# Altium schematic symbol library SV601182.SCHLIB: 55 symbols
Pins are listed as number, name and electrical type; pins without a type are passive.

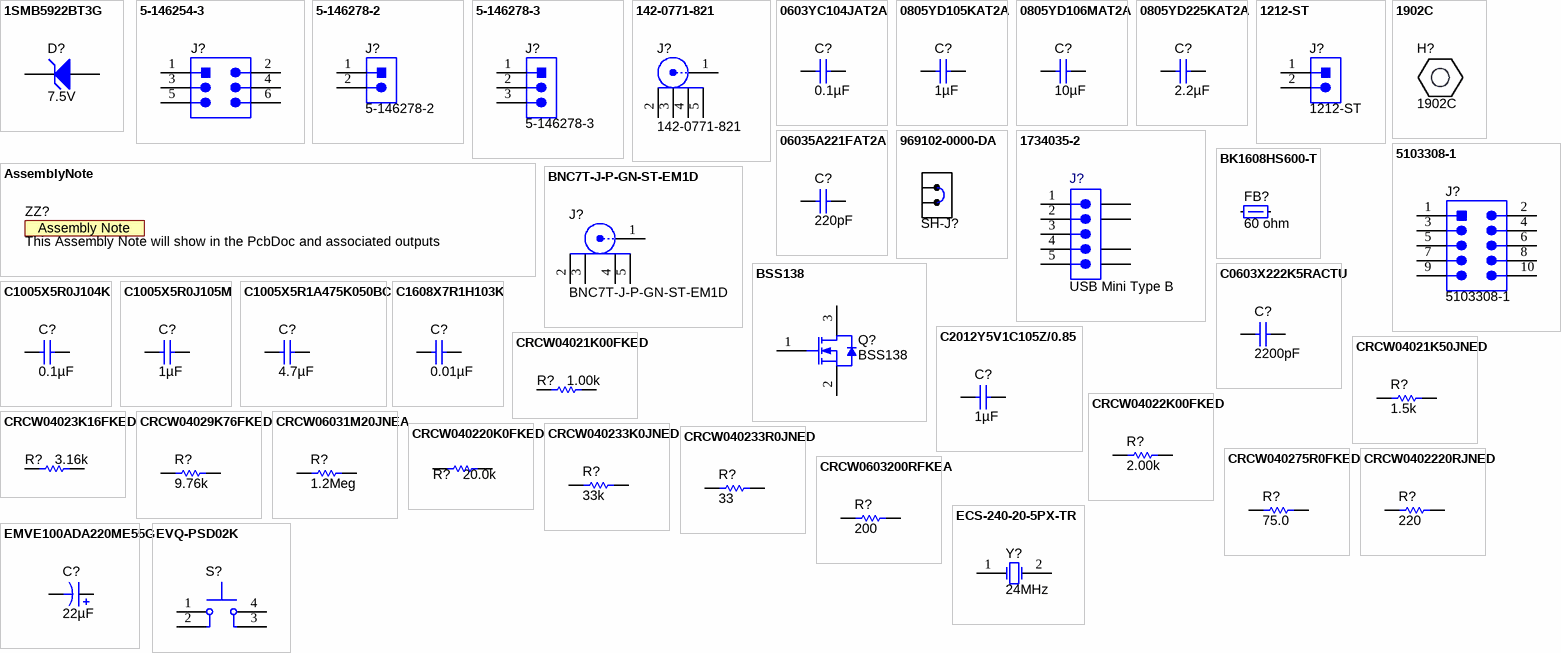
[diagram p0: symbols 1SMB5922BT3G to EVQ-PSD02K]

## 1SMB5922BT3G
designator D?  value 7.5V  (hidden comment: 1SMB5922BT3G)
Diode, Zener, 7.5 V, 550 mW, SMB; Manufacturer: ON Semiconductor; SymbolCreator: a0412235; U/M: EA; Power_W: 0.55; Vz_V: 7.5; Value1: 0.55W; RJA_CperW: 226
signal-integrity model Diode
simulation model 1smb5922bt3
footprint SMB
pins: 1 K, 2 A

## 5-146254-3
designator J?  (value not drawn)
Header, 100mil, 3x2, Tin, TH; Manufacturer: TE Connectivity; SymbolCreator: a0412235; U/M: EA
footprint TE_5-146254-3
pins: 1, 2, 3, 4, 5, 6

## 5-146278-2
designator J?
Header, 100mil, 2x1, Tin, TH; Manufacturer: TE Connectivity; SymbolCreator: a0412235; U/M: EA
footprint TE_5-146278-2
pins: 1, 2
1 alternate drawing of the same symbol

## 5-146278-3
designator J?
Header, 100mil, 3x1, Tin, TH; Manufacturer: TE Connectivity; SymbolCreator: a0799628; U/M: EA
footprint TE_5-146278-3
pins: 1, 2, 3
2 alternate drawings of the same symbol

## 142-0771-821
designator J?
Connector, TH, End launch SMA 50 ohm; Manufacturer: Emerson Network Power; SymbolCreator: X0208326; U/M: EA
footprint Emerson_142-0771-821
pins: 1, 2, 3, 4, 5

## 0603YC104JAT2A
designator C?  ValueDisplayed: 0.1µF  (hidden comment: 0603YC104JAT2A)
CAP, CERM, 0.1uF, 16V, +/-5%, X7R, 0603; Manufacturer: AVX; Polarized: N; CompType: Capacitor; U/M: EA; Cap_F: 0.0000001; Tolerance_%: 5; ESR_Ohm: 0.039; Value1: 0.039 ohm; VDC_V: 16; TaMin_C: -55; TaMax_C: 125; Cap_Case: 0603
signal-integrity model Cap
simulation model Cap
footprint 0603
footprint 0603M
footprint 0603L
footprint 0603_HV
footprint C603
pins: 1, 2

## 0805YD105KAT2A
designator C?  ValueDisplayed: 1µF  (hidden comment: 0805YD105KAT2A)
CAP, CERM, 1uF, 16V, +/-10%, X5R, 0805; Manufacturer: AVX; Polarized: N; CompType: Capacitor; U/M: EA; Cap_F: 0.000001; Tolerance_%: 10; ESR_Ohm: 0.012; Value1: 0.012 ohm; VDC_V: 16; TaMin_C: -55; TaMax_C: 85; Cap_Case: 0805
signal-integrity model Cap
simulation model Cap
footprint 0805_HV
footprint 0805
footprint 0805M
footprint 0805L
pins: 1, 2

## 0805YD106MAT2A
designator C?  ValueDisplayed: 10µF  (hidden comment: 0805YD106MAT2A)
CAP, CERM, 10uF, 16V, +/-20%, X5R, 0805; Manufacturer: AVX; Polarized: N; CompType: Capacitor; U/M: EA; Cap_F: 0.00001; Tolerance_%: 20; Value1: Unknown; VDC_V: 16; TaMin_C: -55; TaMax_C: 85; Cap_Case: 0805
signal-integrity model Cap
simulation model Cap
footprint 0805_HV
footprint 0805
footprint 0805M
footprint 0805L
pins: 1, 2

## 0805YD225KAT2A
designator C?  ValueDisplayed: 2.2µF  (hidden comment: 0805YD225KAT2A)
CAP, CERM, 2.2uF, 16V, +/-10%, X5R, 0805; Manufacturer: AVX; Polarized: N; CompType: Capacitor; U/M: EA; Cap_F: 0.0000022; Tolerance_%: 10; ESR_Ohm: 0.009; Value1: 0.009 ohm; VDC_V: 16; TaMin_C: -55; TaMax_C: 85; Cap_Case: 0805
signal-integrity model Cap
simulation model Cap
footprint 0805_HV
footprint 0805
footprint 0805M
footprint 0805L
footprint C0805
pins: 1, 2

## 1212-ST
designator J?
Disconnect Terminal, 5.08mm, 2x1, Tin, TH; Manufacturer: Keystone; SymbolCreator: a0412235; U/M: EA
footprint Keystone_1212-ST
pins: 1, 2
1 alternate drawing of the same symbol

## 1902C
designator H?
Standoff, Hex, 0.5"L #4-40 Nylon; Manufacturer: Keystone; CompType: Hardware; SymbolCreator: a0412235
footprint Keystone_1902C

## 06035A221FAT2A
designator C?  ValueDisplayed: 220pF  (hidden comment: 06035A221FAT2A)
CAP, CERM, 220pF, 50V, +/-1%, C0G/NP0, 0603; Manufacturer: AVX; Polarized: N; CompType: Capacitor; U/M: EA; Cap_F: 0.00000000022; Tolerance_%: 1; ESR_Ohm: 0.083; Value1: 0.083 ohm; VDC_V: 50; TaMin_C: -55; TaMax_C: 125; Cap_Case: 0603
signal-integrity model Cap
simulation model Cap
footprint 0603
footprint 0603M
footprint 0603L
footprint 0603_HV
footprint C603
pins: 1, 2

## 969102-0000-DA
designator SH-J?  (value not drawn)
Shunt, 100mil, Gold plated, Black; Manufacturer: 3M; Alternate Manufacturer: Samtec; Alternate PartNumber: SNT-100-BK-G; Value: 1x2; Note: You can "mate" this to a header by matching the designator.  i.e. use SH-J3 for header J3
footprint SNT-100-BK-G

## 1734035-2
designator J?, comment USB Mini Type B
Connector, Receptacle, Mini-USB Type B, R/A, Top Mount SMT; Manufacturer: TE Connectivity; PartNumber: 1734035-2; SymbolCreator: A0412235; U/M: EA
footprint CONN_USB-Mini-B-1734035-2
pins: 1, 2, 3, 4, 5, 6 GND, 7 GND, 8 GND, 9 GND

## 5103308-1
designator J?
Header (shrouded), 100mil, 5x2, Gold, TH; Manufacturer: TE Connectivity; SymbolCreator: a0412235; U/M: EA
footprint CONN_5103308-1
pins: 1, 2, 3, 4, 5, 6, 7, 8, 9, 10

## AssemblyNote
designator ZZ?, comment This Assembly Note will show in the PcbDoc and associated outputs  (no BOM)
SymbolCreator: codlsc
footprint AssemblyNote

## BK1608HS600-T
designator FB?  value 60 ohm  (hidden comment: BK1608HS600-T)
Ferrite Bead, 60 ohm @ 100 MHz, 0.8 A, 0603; Manufacturer: Taiyo Yuden; Imax_A: 0.8; DCR_ohm: 0.1; Value1: 0.1 ohm; Value2: 0.8A; ZTyp@100MHz_Ohm: 60
footprint 0603
footprint 0603M
footprint 0603L
footprint 0603_HV
footprint 0603S
pins: 1, 2

## BNC7T-J-P-GN-ST-EM1D
designator J?
Connector, BNC Edge Mount, SMD; Manufacturer: Samtec; SymbolCreator: Altium; U/M: EA
footprint SAMTEC_BNC7T-J-P-GN-ST-EM1D
pins: 1, 2, 3, 4, 5

## BSS138
designator Q?
MOSFET, N-CH, 50 V, 0.22 A, SOT-23; Manufacturer: Fairchild Semiconductor; Alternate Manufacturer: None; U/M: EA; ChType: N; Value: 50V; VdsMax_V: 50; Value1: 6 ohm; Rdson45_ohm: 6; Value2: 1.7 nC; QgTyp_nC: 1.7; Vgs_V: 20; IdsMax_A: 0.22
footprint SOT-23
footprint SOT-23M
footprint SOT-23L
pins: 1 G, 2 S, 3 D

## C0603X222K5RACTU
designator C?  ValueDisplayed: 2200pF  (hidden comment: C0603X222K5RACTU)
CAP, CERM, 2200pF, 50V, +/-10%, X7R, 0603; Manufacturer: Kemet; Polarized: N; CompType: Capacitor; U/M: EA; Cap_F: 0.0000000022; Tolerance_%: 10; VDC_V: 50; TaMin_C: -55; TaMax_C: 125; Cap_Case: 0603
signal-integrity model Cap
simulation model Cap
footprint 0603
footprint 0603M
footprint 0603L
footprint 0603_HV
footprint C603
pins: 1, 2

## C1005X5R0J104K
designator C?  ValueDisplayed: 0.1µF  (hidden comment: C1005X5R0J104K)
CAP, CERM, 0.1uF, 6.3V, +/-10%, X5R, 0402; Manufacturer: TDK; Polarized: N; CompType: Capacitor; U/M: EA; Cap_F: 0.0000001; Tolerance_%: 10; ESR_Ohm: 0.0186; Value1: 0.0186 ohm; VDC_V: 6.3; TaMin_C: -55; TaMax_C: 85; Cap_Case: 0402
signal-integrity model Cap
simulation model Cap
footprint 0402
footprint 0402M
footprint 0402L
footprint 0402S
pins: 1, 2

## C1005X5R0J105M
designator C?  ValueDisplayed: 1µF  (hidden comment: C1005X5R0J105M)
CAP, CERM, 1 µF, 6.3 V, +/- 20%, X5R, 0402; Manufacturer: TDK; Polarized: N; CompType: Capacitor; Value: 1uF; U/M: EA; Cap_F: 0.000001; Tolerance_%: 20; ESR_ohm: 0.0079; Value1: 0.0079 ohm; VDC_V: 6.3; Value2: 6.3V; TaMin_C: -55; TaMax_C: 85; Cap_Case: 0402
signal-integrity model Cap
simulation model Cap
footprint 0402
footprint 0402M
footprint 0402L
footprint 0402S
pins: 1, 2

## C1005X5R1A475K050BC
designator C?  ValueDisplayed: 4.7µF  (hidden comment: C1005X5R1A475K050BC)
CAP, CERM, 4.7 µF, 10 V, +/- 10%, X5R, 0402; Manufacturer: TDK; Polarized: N; CompType: Capacitor; Value: 4.7uF; U/M: EA; Cap_F: 0.0000047; Tolerance_%: 10; Value1: Unknown; Value2: 10V; TaMin_C: -55; TaMax_C: 85; Cap_Case: 0402
signal-integrity model Cap
simulation model Cap
footprint 0402
footprint 0402M
footprint 0402L
footprint 0402S
pins: 1, 2

## C1608X7R1H103K
designator C?  ValueDisplayed: 0.01µF  (hidden comment: C1608X7R1H103K)
CAP, CERM, 0.01uF, 50V, +/-10%, X7R, 0603; Manufacturer: TDK; Polarized: N; CompType: Capacitor; U/M: EA; Cap_F: 0.00000001; Tolerance_%: 10; ESR_Ohm: 0.0539; Value1: 0.0539 ohm; VDC_V: 50; TaMin_C: -55; TaMax_C: 125; Cap_Case: 0603
signal-integrity model Cap
simulation model Cap
footprint 0603
footprint 0603M
footprint 0603L
footprint 0603_HV
footprint C603
pins: 1, 2

## C2012Y5V1C105Z/0.85
designator C?, comment ValueDisplayed: 1µF  (hidden comment: C2012X7R1C105K/1.25)
CAP CER 1UF 16V 10% X7R 0805; Manufacturer: TDK; Polarized: N; CompType: Capacitor; U/M: EA; Cap_F: 0.000001; Tolerance_%: 80; ESR_Ohm: 0.009; Value1: 0.009 ohm; VDC_V: 16; TaMin_C: -30; TaMax_C: 85; Cap_Case: 0805
signal-integrity model Cap
simulation model Cap
footprint 0805_HV
footprint 0805
footprint 0805M
footprint 0805L
footprint C0805
pins: 1, 2

## CRCW04021K00FKED
designator R?  value 1.00k  (hidden comment: CRCW04021K00FKED)
RES, 1.00k ohm, 1%, 0.063W, 0402; Manufacturer: Vishay-Dale; CompType: Resistor; Res_ohm: 1000; Value_Code: 1k00; Tolerance_%: 1; Power_W: 0.063; VDC_V: 50; TempCo: 100 ppm/C; EIA_Code: E96; U/M: EA
signal-integrity model Resistor
simulation model Resistor
footprint 0402
footprint 0402M
footprint 0402L
footprint 0402S
pins: 1, 2

## CRCW04021K50JNED
designator R?  value 1.5k  (hidden comment: CRCW04021K50JNED)
RES, 1.5k ohm, 5%, 0.063W, 0402; Manufacturer: Vishay-Dale; CompType: Resistor; Res_ohm: 1500; Value_Code: 1k50; Tolerance_%: 5; Power_W: 0.063; VDC_V: 50; TempCo: 200 ppm/C; EIA_Code: E24; U/M: EA
signal-integrity model Resistor
simulation model Resistor
footprint 0402
footprint 0402M
footprint 0402L
footprint 0402
pins: 1, 2

## CRCW04022K00FKED
designator R?  value 2.00k  (hidden comment: CRCW04022K00FKED)
RES, 2.00k ohm, 1%, 0.063W, 0402; Manufacturer: Vishay-Dale; CompType: Resistor; Res_ohm: 2000; Value_Code: 2k00; Tolerance_%: 1; Power_W: 0.063; VDC_V: 50; TempCo: 100 ppm/C; EIA_Code: E96; U/M: EA
signal-integrity model Resistor
simulation model Resistor
footprint 0402
footprint 0402M
footprint 0402L
footprint 0402S
pins: 1, 2

## CRCW04023K16FKED
designator R?  value 3.16k  (hidden comment: CRCW04023K16FKED)
RES, 3.16k ohm, 1%, 0.063W, 0402; Manufacturer: Vishay-Dale; CompType: Resistor; Res_ohm: 3160; Value_Code: 3k16; Tolerance_%: 1; Power_W: 0.063; VDC_V: 50; TempCo: 100 ppm/C; EIA_Code: E96; U/M: EA
signal-integrity model Resistor
simulation model Resistor
footprint 0402
footprint 0402M
footprint 0402L
footprint 0402S
pins: 1, 2

## CRCW04029K76FKED
designator R?  value 9.76k  (hidden comment: CRCW04029K76FKED)
RES, 9.76k ohm, 1%, 0.063W, 0402; Manufacturer: Vishay-Dale; CompType: Resistor; Res_ohm: 9760; Value_Code: 9k76; Tolerance_%: 1; Power_W: 0.063; VDC_V: 50; TempCo: 100 ppm/C; EIA_Code: E96; U/M: EA
signal-integrity model Resistor
simulation model Resistor
footprint 0402
footprint 0402M
footprint 0402L
footprint 0402S
pins: 1, 2

## CRCW06031M20JNEA
designator R?  value 1.2Meg  (hidden comment: CRCW06031M20JNEA)
RES, 1.2Meg ohm, 5%, 0.1W, 0603; Manufacturer: Vishay-Dale; CompType: Resistor; Res_ohm: 1200000; Value_Code: 1M20; Tolerance_%: 5; Power_W: 0.1; VDC_V: 75; TempCo: 200 ppm/C; EIA_Code: E24; U/M: EA
signal-integrity model Resistor
simulation model Resistor
footprint 0603
footprint 0603M
footprint 0603L
footprint 0603_HV
footprint R603
pins: 1, 2

## CRCW040220K0FKED
designator R?  value 20.0k  (hidden comment: CRCW040220K0FKED)
RES, 20.0k ohm, 1%, 0.063W, 0402; Manufacturer: Vishay-Dale; CompType: Resistor; Res_ohm: 20000; Value_Code: 20k0; Tolerance_%: 1; Power_W: 0.063; VDC_V: 50; TempCo: 100 ppm/C; EIA_Code: E96; U/M: EA
signal-integrity model Resistor
simulation model Resistor
footprint 0402
footprint 0402M
footprint 0402L
footprint 0402S
pins: 1, 2

## CRCW040233K0JNED
designator R?  value 33k  (hidden comment: CRCW040233K0JNED)
RES, 33k ohm, 5%, 0.063W, 0402; Manufacturer: Vishay-Dale; CompType: Resistor; Res_ohm: 33000; Value_Code: 33k0; Tolerance_%: 5; Power_W: 0.063; VDC_V: 50; TempCo: 200 ppm/C; EIA_Code: E24; U/M: EA
signal-integrity model Resistor
simulation model Resistor
footprint 0402
footprint 0402M
footprint 0402L
pins: 1, 2

## CRCW040233R0JNED
designator R?  value 33  (hidden comment: CRCW040233R0JNED)
RES, 33 ohm, 5%, 0.063W, 0402; Manufacturer: Vishay-Dale; CompType: Resistor; Value_Code: 33R0; Tolerance_%: 5; Power_W: 0.063; VDC_V: 50; TempCo: 200 ppm/C; EIA_Code: E24; U/M: EA
signal-integrity model Resistor
simulation model Resistor
footprint 0402
footprint 0402M
footprint 0402L
footprint 0402
pins: 1, 2

## CRCW040275R0FKED
designator R?  value 75.0  (hidden comment: CRCW040275R0FKED)
RES, 75.0 ohm, 1%, 0.063W, 0402; Manufacturer: Vishay-Dale; CompType: Resistor; Res_ohm: 75; Value_Code: 75R0; Tolerance_%: 1; Power_W: 0.063; VDC_V: 50; TempCo: 100 ppm/C; EIA_Code: E96; U/M: EA
signal-integrity model Resistor
simulation model Resistor
footprint 0402
footprint 0402M
footprint 0402L
footprint 0402S
pins: 1, 2

## CRCW0402220RJNED
designator R?  value 220  (hidden comment: CRCW0402220RJNED)
RES, 220 ohm, 5%, 0.063W, 0402; Manufacturer: Vishay-Dale; CompType: Resistor; Value_Code: 220R; Tolerance_%: 5; Power_W: 0.063; VDC_V: 50; TempCo: 200 ppm/C; EIA_Code: E24; U/M: EA
signal-integrity model Resistor
simulation model Resistor
footprint 0402
footprint 0402M
footprint 0402L
footprint 0402S
pins: 1, 2

## CRCW0603200RFKEA
designator R?  value 200  (hidden comment: CRCW0603200RFKEA)
RES, 200 ohm, 1%, 0.1W, 0603; Manufacturer: Vishay-Dale; CompType: Resistor; Value_Code: 200R; Tolerance_%: 1; Power_W: 0.1; VDC_V: 75; TempCo: 100 ppm/C; EIA_Code: E96; U/M: EA
signal-integrity model Resistor
simulation model Resistor
footprint 0603
footprint 0603M
footprint 0603L
footprint 0603_HV
footprint R603
pins: 1, 2

## ECS-240-20-5PX-TR
designator Y?  Frequency: 24MHz  (hidden comment: ECS-240-20-5PX-TR)
Crystal, 24.000MHz, 20pF, SMD; Manufacturer: ECS Inc.; SymbolCreator: a0412235; U/M: EA; TaMin_C: -10; TaMax_C: 70; Frequency Stability: ±50ppm
footprint XTAL_CSM-7X
pins: 1 OSC1, 2 OSC2

## EMVE100ADA220ME55G
designator C?, comment ValueDisplayed: 22µF  (hidden comment: EEE-1AA220WR)
CAP ALUM 22UF 10V 20% SMD; Manufacturer: Panasonic - ECG; Polarized: Y; CompType: Capacitor; U/M: EA; Cap_F: 0.000022; Tolerance_%: 20; VDC_V: 10; IRMS_A: 0.03; TaMin_C: -40; TaMax_C: 105; Cap_Case: E55
signal-integrity model Cap
simulation model Cap
footprint CAPSMT_62_E55
pins: 1 +, 2 -

## EVQ-PSD02K
designator S?  (value not drawn)
Switch, Tactile, SPST-NO, SMT; Manufacturer: Panasonic; SymbolCreator: a0799628; VDC_V: 12; SwitchFunction: Off-Mom; PositionCount: 1; CurrentRating_mA: 50
footprint SW_EVQ-PSD02K
pins: 1, 2, 3, 4

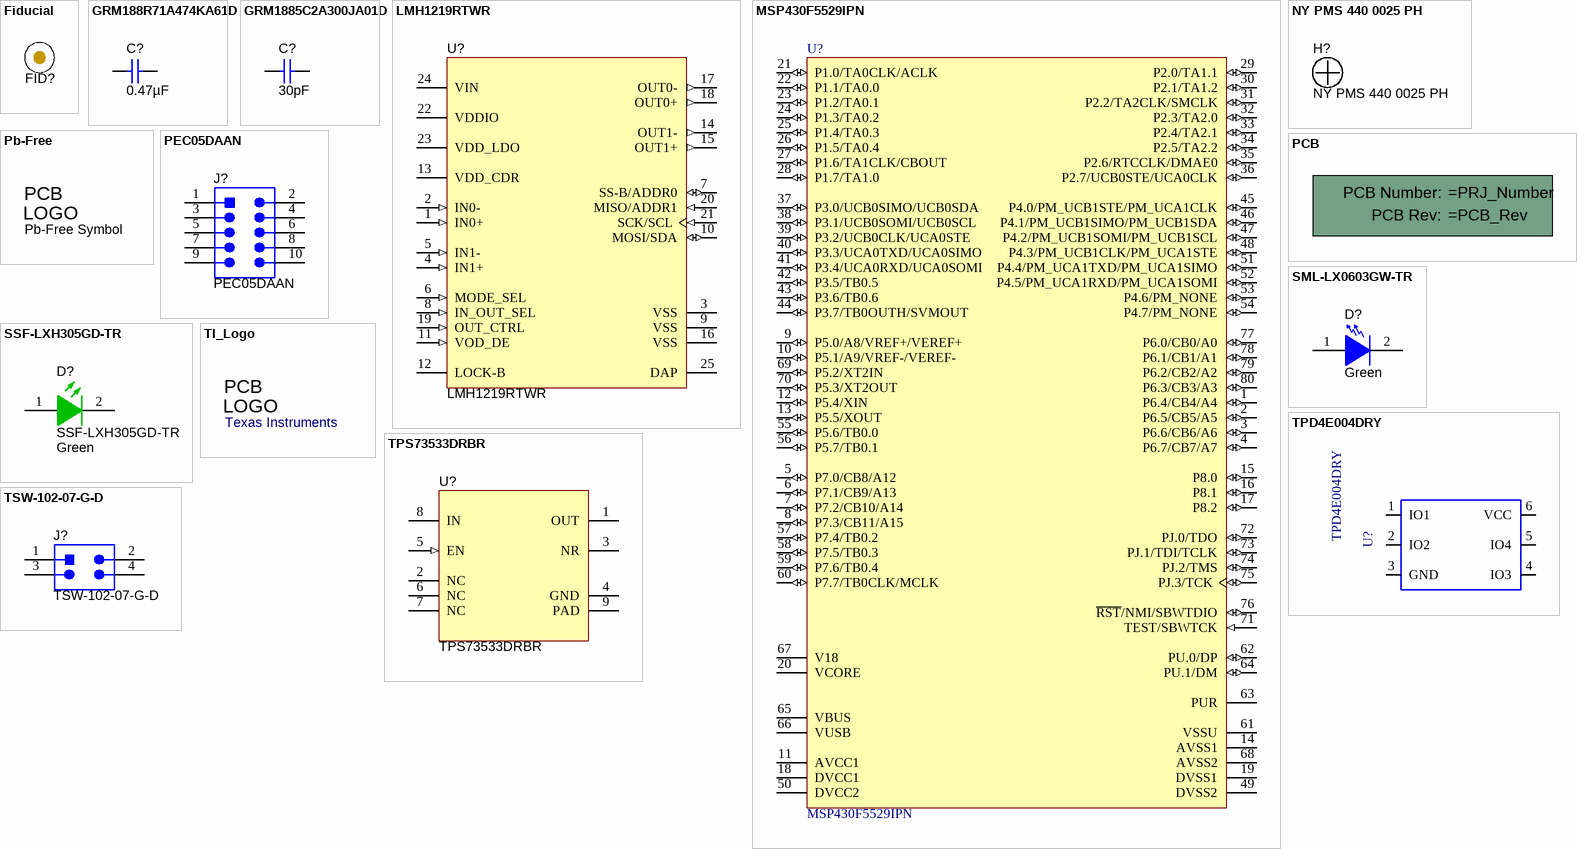
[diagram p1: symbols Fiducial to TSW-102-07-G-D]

## Fiducial
designator FID?  (value not drawn)
Fiducial mark.  There is nothing to buy or mount.; SymbolCreator: codlsc
footprint Fiducial10-30
footprint Fiducial10-20
footprint Fiducial15-30
footprint Fiducial20-40
footprint Fiducial6.4-20
footprint Fiducial10-30_Panel

## GRM188R71A474KA61D
designator C?  ValueDisplayed: 0.47µF  (hidden comment: GRM188R71A474KA61D)
CAP, CERM, 0.47uF, 10V, +/-10%, X7R, 0603; Manufacturer: MuRata; Polarized: N; CompType: Capacitor; U/M: EA; Cap_F: 0.00000047; Tolerance_%: 10; TaMin_C: -55; TaMax_C: 125; Cap_Case: 0603
signal-integrity model Cap
simulation model Cap
footprint 0603
footprint 0603M
footprint 0603L
footprint 0603_HV
footprint C603
pins: 1, 2

## GRM1885C2A300JA01D
designator C?  ValueDisplayed: 30pF  (hidden comment: GRM1885C2A300JA01D)
CAP, CERM, 30pF, 100V, +/-5%, C0G/NP0, 0603; Manufacturer: MuRata; Polarized: N; CompType: Capacitor; U/M: EA; Cap_F: 0.00000000003; Tolerance_%: 5; VDC_V: 100; TaMin_C: -55; TaMax_C: 125; Cap_Case: 0603
signal-integrity model Cap
simulation model Cap
footprint 0603
footprint 0603M
footprint 0603L
footprint 0603_HV
footprint C603
pins: 1, 2

## LMH1219RTWR
designator U?
Low Power 12G UHD Adaptive Cable Equalizer with Integrated Reclocker, RTW0024A; Alternate PartNumber: LMH1219RTWT; Manufacturer: Texas Instruments; SymbolCreator: Altium; CompType: IC; U/M: EA
footprint RTW0024A
pins: 1 IN0+ (in), 2 IN0- (in), 3 VSS (power), 4 IN1+ (in), 5 IN1- (in), 6 MODE_SEL (in), 7 SS-B/ADDR0 (io), 8 IN_OUT_SEL (in), 9 VSS (power), 10 MOSI/SDA (io), 11 VOD_DE (in), 12 LOCK-B (oc), 13 VDD_CDR (power), 14 OUT1- (out), 15 OUT1+ (out), 16 VSS (power), 17 OUT0- (out), 18 OUT0+ (out), 19 OUT_CTRL (in), 20 MISO/ADDR1 (in), 21 SCK/SCL (in), 22 VDDIO (power), 23 VDD_LDO (power), 24 VIN (power), 25 DAP (power)

## MSP430F5529IPN
designator U?
25 MHz Mixed Signal Microcontroller with 128 KB Flash, 8192 B SRAM and 63 GPIOs, -40 to 85 degC, 80-pin QFP (PN), Green (RoHS & no Sb/Br); Manufacturer: Texas Instruments; Alternate PartNumber: Equivalent; ADC: 12-bit SAR; ADC Channels: 16; Brown Out Reset: Yes; DMA: 3; Flash(KB): 128; Frequency(MHz): 25; GPIO: 63; Multiplier: 32x32; Pin/Package: 0DIESALE, 80LQFP; SRAM(B): 8192; SubFamily: 5 Series; Timers - 16-bit: 4; USB: 1; USCI_A (UART/LIN/IrDA/SPI): 2
footprint PN0080A_N (QFP, 80-Leads, Body 12x12mm, Pitch 0.5mm, IPC Medium Density)
footprint PN0080A_L (QFP, 80-Leads, Body 12x12mm, Pitch 0.5mm, IPC High Density)
footprint PN0080A_M (QFP, 80-Leads, Body 12x12mm, Pitch 0.5mm, IPC Low Density)
pins: 1 P6.4/CB4/A4 (io), 2 P6.5/CB5/A5 (io), 3 P6.6/CB6/A6 (io), 4 P6.7/CB7/A7 (io), 5 P7.0/CB8/A12 (io), 6 P7.1/CB9/A13 (io), 7 P7.2/CB10/A14 (io), 8 P7.3/CB11/A15 (io), 9 P5.0/A8/VREF+/VEREF+ (io), 10 P5.1/A9/VREF-/VEREF- (io), 11 AVCC1 (power) "Analog power supply", 12 P5.4/XIN (io), 13 P5.5/XOUT (io), 14 AVSS1 (power) "Analog ground supply", 15 P8.0 (io) "General-purpose digital I/O", 16 P8.1 (io) "General-purpose digital I/O", 17 P8.2 (io) "General-purpose digital I/O", 18 DVCC1 (power) "Digital power supply", 19 DVSS1 (power) "Digital ground supply", 20 VCORE "Regulated core power supply output (internal use only, no external current loading)", 21 P1.0/TA0CLK/ACLK (io), 22 P1.1/TA0.0 (io), 23 P1.2/TA0.1 (io), 24 P1.3/TA0.2 (io), 25 P1.4/TA0.3 (io), 26 P1.5/TA0.4 (io), 27 P1.6/TA1CLK/CBOUT (io), 28 P1.7/TA1.0 (io), 29 P2.0/TA1.1 (io), 30 P2.1/TA1.2 (io), 31 P2.2/TA2CLK/SMCLK (io), 32 P2.3/TA2.0 (io), 33 P2.4/TA2.1 (io), 34 P2.5/TA2.2 (io), 35 P2.6/RTCCLK/DMAE0 (io), 36 P2.7/UCB0STE/UCA0CLK (io), 37 P3.0/UCB0SIMO/UCB0SDA (io), 38 P3.1/UCB0SOMI/UCB0SCL (io), 39 P3.2/UCB0CLK/UCA0STE (io), 40 P3.3/UCA0TXD/UCA0SIMO (io), 41 P3.4/UCA0RXD/UCA0SOMI (io), 42 P3.5/TB0.5 (io), 43 P3.6/TB0.6 (io), 44 P3.7/TB0OUTH/SVMOUT (io), 45 P4.0/PM_UCB1STE/PM_UCA1CLK (io), 46 P4.1/PM_UCB1SIMO/PM_UCB1SDA (io), 47 P4.2/PM_UCB1SOMI/PM_UCB1SCL (io), 48 P4.3/PM_UCB1CLK/PM_UCA1STE (io), 49 DVSS2 (power) "Digital ground supply", 50 DVCC2 (power) "Digital power supply", 51 P4.4/PM_UCA1TXD/PM_UCA1SIMO (io), 52 P4.5/PM_UCA1RXD/PM_UCA1SOMI (io), 53 P4.6/PM_NONE (io), 54 P4.7/PM_NONE (io), 55 P5.6/TB0.0 (io), 56 P5.7/TB0.1 (io), 57 P7.4/TB0.2 (io), 58 P7.5/TB0.3 (io), 59 P7.6/TB0.4 (io), 60 P7.7/TB0CLK/MCLK (io), 61 VSSU (power) "USB PHY ground supply", 62 PU.0/DP (io), 63 PUR "USB pullup resistor pin (open drain). The voltage level at the PUR pin is used to invoke the default USB BSL. Recommended 1-Mohm resistor to ground.", 64 PU.1/DM (io), 65 VBUS (power) "USB LDO input (connect to USB power source)", 66 VUSB (power) "USB LDO output", 67 V18 "USB regulated power (internal use only, no external current loading)", 68 AVSS2 (power) "Analog ground supply", 69 P5.2/XT2IN (io), 70 P5.3/XT2OUT (io), 71 TEST/SBWTCK (in), 72 PJ.0/TDO (io), 73 PJ.1/TDI/TCLK (io), 74 PJ.2/TMS (io), 75 PJ.3/TCK (io), 76 ~{RST}/NMI/SBWTDIO (io), 77 P6.0/CB0/A0 (io), 78 P6.1/CB1/A1 (io), 79 P6.2/CB2/A2 (io), 80 P6.3/CB3/A3 (io)

## NY PMS 440 0025 PH
designator H?
Machine Screw, Round, #4-40 x 1/4, Nylon, Philips panhead; Manufacturer: B&F Fastener Supply; CompType: Hardware; SymbolCreator: codlsc; U/M: EA
footprint NY PMS 440 0025 PH
footprint NY PMS 440 0025 PH_3Donly

## Pb-Free
designator Logo?, comment Pb-Free Symbol  (no BOM)
SymbolCreator: a0412235
footprint Pb-Free_Overlay_Medium
footprint Pb-Free_Overlay_Small

## PCB
designator !PCB?, comment Printed Circuit Board  (value not drawn)  (mechanical)
Manufacturer: Any; SymbolCreator: a0412235; CompType: PCB
1 alternate drawing of the same symbol

## PEC05DAAN
designator J?
Header, 100mil, 5x2, Tin, TH; Manufacturer: Sullins Connector Solutions; SymbolCreator: a0412235; U/M: EA
footprint CONN_PEC05DAAN
pins: 1, 2, 3, 4, 5, 6, 7, 8, 9, 10

## SML-LX0603GW-TR
designator D?  value Green  (hidden comment: SML-LX0603GW-TR)
LED, Green, SMD; Manufacturer: Lumex; Vf_V: 2.2; Value2: 2.2V; Io_A: 0.02; Tjmax_C: 85; Value1: W; U/M: EA
signal-integrity model Diode
footprint LED_SML-LX0603GW
pins: 1 A, 2 K

## SSF-LXH305GD-TR
designator D?  value Green
LED, Green, SMD; Manufacturer: Lumex; SymbolCreator: Altium; Vf_V: 2.2; Value2: 2.2V; Io_A: 0.02; Vr_V: 5; Ir_A: 0.0001; Tjmax_C: 85; Value1: W; Angle: 60; U/M: EA
footprint SSF-LXH305GD_Green
pins: 1 A, 2 K

## TI_Logo
designator Logo?, comment Texas Instruments  (no BOM)
Texas Instrument Corporate Signature; SymbolCreator: a0412235
footprint TI_Stacked_SolderMask_Medium
footprint TI_Stacked_SolderMask_Medium_Vertical
footprint TI_Stacked_SolderMask_Small
footprint TI_Stacked_SolderMask_Small_Vertical
footprint TI_Stacked_Overlay_Medium
footprint TI_Stacked_Overlay_Medium_Vertical
footprint TI_Stacked_Overlay_Small
footprint TI_Stacked_Overlay_Small_Vertical
footprint TI_Horizontal_SolderMask_Small
footprint TI_Horizontal_Overlay_Medium
footprint TI_Horizontal_Overlay_Small
footprint TI_Symbol_SolderMask_Medium
footprint TI_Symbol_SolderMask_Small
footprint TI_Symbol_Overlay_Medium
footprint TI_Symbol_Overlay_Small
footprint TI_Horizontal_SolderMask_Medium

## TPD4E004DRY
designator U?
IC, 4-Chan ESD-Protection Array; Manufacturer: Texas Instruments; Second Source: C:\program files\p-cad 2004\pcad_pdf's\tpd4e004.pdf; Reference: \\vette02\pmp_pcb\pcad_pdf's\tpd4e004.pdf; Area: 3.883 mm; PCB DECAL: DRY
footprint DRY
pins: 1 IO1, 2 IO2, 3 GND, 4 IO3, 5 IO4, 6 VCC

## TPS73533DRBR
designator U?
500mA, Low Quiescent Current, Ultra-Low Noise, High PSRR Low-Dropout Linear Regulator, DRB0008A; Manufacturer: Texas Instruments; Alternate PartNumber: TPS73533DRBT; SymbolCreator: Altium; CompType: IC; U/M: EA
footprint DRB0008A
pins: 1 OUT (power), 2 NC, 3 NR, 4 GND (power), 5 EN (in), 6 NC, 7 NC, 8 IN (power), 9 PAD (power)

## TSW-102-07-G-D
designator J?
Header, 100mil, 2x2, Gold, TH; Manufacturer: Samtec; SymbolCreator: a0412235; U/M: EA
footprint TSW-102-07-G-D
pins: 1, 2, 3, 4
